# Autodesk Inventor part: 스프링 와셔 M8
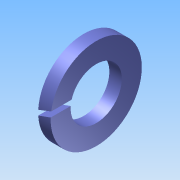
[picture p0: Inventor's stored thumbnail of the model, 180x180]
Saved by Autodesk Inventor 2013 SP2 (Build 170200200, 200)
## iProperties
Created: 2025-10
Part Number: 스프링 와셔 M8
Material: Generic
Document SubType Name: Modeling
Designer: 601
Density: 1 g/cm^3
Author: 601
변환 표준: STEP AP214IS
전처리기: Build: 200, Release: 2013 SP2 Update 6 - Date: Thu 07/17/2014
전송 단위: 밀리미터
불확실성: 0.01
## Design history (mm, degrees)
node "스프링 와셔 M81"
body "Solid1"
node "기준1"
